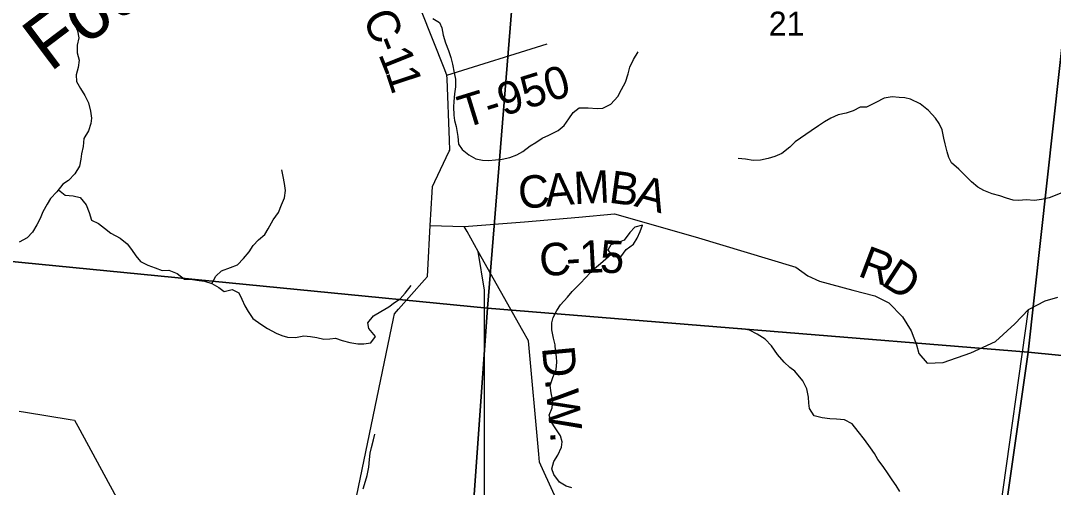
# Model space of a CAD drawing. Extents: x 0 to 42, y 0 to 22.
# Drawn here: x 2.747 to 3.649, y 17.518 to 17.925 of the extents above; entities that cross this region are included whole.
import ezdxf

# ---------------------------------------------------------------- set-up
doc = ezdxf.new("R2010")
doc.units = 0
for name, color, linetype in [('GM_X_County_Road', 7, 'Continuous'), ('GM_X_County_Road_Text', 7, 'Continuous'), ('GM_X_Minor_Lake', 7, 'Continuous'), ('GM_X_Minor_River', 7, 'Continuous'), ('GM_X_Minor_River_Text', 7, 'Continuous'), ('GM_X_Section', 7, 'Continuous'), ('GM_X_Section_Text', 7, 'Continuous'), ('GM_X_Township_Road', 7, 'Continuous'), ('GM_X_Township_Road_Text', 7, 'Continuous')]:
    doc.layers.add(name, color=color, linetype=linetype)

msp = doc.modelspace()

# ---------------------------------------------------------------- linework, layer by layer
at = {"layer": 'GM_X_County_Road'}
for points in [[(3.00848, 17.35497), (3.07286, 17.6651), (3.07373, 17.66937), (3.07729, 17.67338), (3.09993, 17.69889), (3.10256, 17.70184), (3.10288, 17.70762), (3.10505, 17.74655), (3.10667, 17.77575), (3.10692, 17.78047), (3.10907, 17.78499), (3.12163, 17.8114), (3.1221, 17.81237), (3.12177, 17.82102), (3.11976, 17.87459), (3.11963, 17.8779), (3.11725, 17.88388), (3.09745, 17.93368)], [(3.10505, 17.74655), (3.13476, 17.74555), (3.1874, 17.74956), (3.23481, 17.75389), (3.26596, 17.75674), (3.33644, 17.73665), (3.42456, 17.71011), (3.43499, 17.70257), (3.44523, 17.69788), (3.47439, 17.69006), (3.49352, 17.68503), (3.50584, 17.67883), (3.51762, 17.66675), (3.52524, 17.65447), (3.52983, 17.64217), (3.53195, 17.63459), (3.53917, 17.62609), (3.55316, 17.62692), (3.57734, 17.63519), (3.59905, 17.64515), (3.61582, 17.66059), (3.62787, 17.67316), (3.64222, 17.68062), (3.65336, 17.6839)]]:
    msp.add_lwpolyline(points, dxfattribs=at)
at = {"layer": 'GM_X_Minor_Lake'}
for points in [[(3.28846, 17.74113), (3.29037, 17.74668), (3.28393, 17.74519), (3.27956, 17.74028), (3.27462, 17.73366), (3.26856, 17.73141), (3.26288, 17.72954), (3.26021, 17.725)], [(3.26021, 17.725), (3.26473, 17.71948), (3.27154, 17.71908), (3.27629, 17.72551), (3.28255, 17.73022), (3.28598, 17.73532), (3.28846, 17.74113)]]:
    msp.add_lwpolyline(points, dxfattribs=at)
at = {"layer": 'GM_X_Minor_River'}
for points in [[(2.79376, 17.9277), (2.79431, 17.92277), (2.79674, 17.9165), (2.79785, 17.91043), (2.79651, 17.90418), (2.79667, 17.89736), (2.79816, 17.8911), (2.79738, 17.88447), (2.79565, 17.87822), (2.79601, 17.87234), (2.79939, 17.86627), (2.80334, 17.86019), (2.80635, 17.85373), (2.80821, 17.84652), (2.80913, 17.84026), (2.80855, 17.83553), (2.80644, 17.82909), (2.80226, 17.82266), (2.80167, 17.81565), (2.80032, 17.80921), (2.79973, 17.80448), (2.79858, 17.79823), (2.79439, 17.79161), (2.78888, 17.78594), (2.78395, 17.78274), (2.77882, 17.77594), (2.77331, 17.77008), (2.77027, 17.76517), (2.76665, 17.75855), (2.76417, 17.75249), (2.76131, 17.74719), (2.75751, 17.74076), (2.75295, 17.73567), (2.74575, 17.7319)], [(3.10737, 17.92744), (3.11303, 17.92401), (3.11509, 17.91926), (3.11639, 17.91281), (3.11845, 17.90617), (3.12107, 17.89934), (3.12294, 17.89326), (3.12443, 17.88738), (3.12592, 17.87998), (3.12703, 17.87429), (3.1272, 17.86766), (3.12623, 17.8616), (3.12564, 17.85478), (3.12524, 17.85004), (3.12578, 17.84303), (3.12633, 17.8381), (3.12764, 17.83297), (3.12912, 17.82425), (3.12966, 17.81761), (3.13286, 17.81286), (3.13871, 17.80829), (3.14475, 17.80467), (3.15061, 17.80351), (3.1559, 17.8033), (3.16196, 17.80384), (3.16782, 17.80439), (3.17445, 17.80588), (3.1807, 17.80832), (3.18582, 17.81114), (3.19227, 17.81605), (3.19738, 17.81906), (3.20288, 17.82283), (3.20876, 17.82546), (3.21672, 17.82941), (3.22203, 17.83394), (3.22621, 17.8398), (3.23001, 17.84509), (3.23514, 17.84943), (3.24289, 17.8494), (3.25083, 17.84861), (3.25594, 17.84916), (3.26295, 17.85255), (3.26884, 17.85916), (3.27227, 17.8654), (3.27551, 17.87164), (3.278, 17.87902), (3.27953, 17.88489), (3.28277, 17.89151), (3.28677, 17.89832)], [(3.65687, 17.77491), (3.6457, 17.77079), (3.63908, 17.76911), (3.63303, 17.76838), (3.62585, 17.76879), (3.61942, 17.76844), (3.61432, 17.76866), (3.60866, 17.77039), (3.60262, 17.77231), (3.59602, 17.77423), (3.58866, 17.77711), (3.58357, 17.77998), (3.57811, 17.78455), (3.57171, 17.79102), (3.56682, 17.7956), (3.5606, 17.80131), (3.55817, 17.80606), (3.55668, 17.81099), (3.55501, 17.81783), (3.55389, 17.82276), (3.55241, 17.82997), (3.54979, 17.83548), (3.5466, 17.84042), (3.54039, 17.84708), (3.53305, 17.8528), (3.52475, 17.85682), (3.51965, 17.85798), (3.51474, 17.85838), (3.50851, 17.85879), (3.5017, 17.85768), (3.49431, 17.85411), (3.48636, 17.84998), (3.48069, 17.84982), (3.47463, 17.84681), (3.46838, 17.84476), (3.46139, 17.84327), (3.45495, 17.84027), (3.44945, 17.83707), (3.44415, 17.83368), (3.43789, 17.82916), (3.43316, 17.82615)], [(3.43316, 17.82615), (3.42388, 17.81952)], [(3.42388, 17.81952), (3.41924, 17.8148), (3.41223, 17.80952), (3.40616, 17.80689), (3.40029, 17.80501), (3.39367, 17.80371), (3.38723, 17.80336), (3.38043, 17.80433), (3.37419, 17.80492)], [(2.91412, 17.69588), (2.91758, 17.70224), (2.9227, 17.70677), (2.93047, 17.70978), (2.93653, 17.71222), (2.94184, 17.71769), (2.94678, 17.72355), (2.95021, 17.72903), (2.95495, 17.73394), (2.96046, 17.73866), (2.96331, 17.74358), (2.96788, 17.75152), (2.97245, 17.75795), (2.97493, 17.76457), (2.9776, 17.77081), (2.97857, 17.77707), (2.97765, 17.78332), (2.97653, 17.7892), (2.97523, 17.79527)], [(2.78023, 17.77781), (2.786, 17.77288), (2.79299, 17.77247), (2.79923, 17.77093), (2.8045, 17.76447), (2.80694, 17.75782), (2.80918, 17.75118), (2.81504, 17.74813), (2.82051, 17.74431), (2.82598, 17.73993), (2.83409, 17.73535), (2.84032, 17.7304), (2.84408, 17.72546), (2.84784, 17.71995), (2.85199, 17.71519), (2.85822, 17.71195), (2.86464, 17.70946), (2.87087, 17.70716), (2.87674, 17.70752), (2.88391, 17.70446), (2.89033, 17.69951), (2.89732, 17.69929), (2.903, 17.69851), (2.90791, 17.69792), (2.91434, 17.69581), (2.92019, 17.69219), (2.92509, 17.68895), (2.93191, 17.69063), (2.93776, 17.68776), (2.94039, 17.68226), (2.94301, 17.67618), (2.94583, 17.67124), (2.94997, 17.66516), (2.95695, 17.66021), (2.9628, 17.65658), (2.97035, 17.65238), (2.97526, 17.65028), (2.98037, 17.64893), (2.98736, 17.64853), (2.99456, 17.65021), (3.00042, 17.64962), (3.0059, 17.64865), (3.01214, 17.6473), (3.01743, 17.64746), (3.02235, 17.64801), (3.02821, 17.6461), (3.03482, 17.64418), (3.04182, 17.6432), (3.04693, 17.64318), (3.05317, 17.64411), (3.05716, 17.6494), (3.05133, 17.65662), (3.0504, 17.66136), (3.05553, 17.6676), (3.06178, 17.67137), (3.0688, 17.67551), (3.07392, 17.67928), (3.07866, 17.68229), (3.08322, 17.68739), (3.08835, 17.6942)], [(3.2288, 17.51739), (3.22389, 17.51874), (3.21785, 17.52217), (3.21296, 17.52902), (3.21127, 17.53395), (3.213, 17.54039), (3.21661, 17.54587), (3.21985, 17.55268), (3.22025, 17.55742), (3.21894, 17.56273), (3.21405, 17.56976), (3.21086, 17.5747), (3.20899, 17.58077), (3.21166, 17.58721), (3.21225, 17.59327), (3.21057, 17.60029), (3.20984, 17.60673), (3.21214, 17.61374), (3.21519, 17.62055), (3.21578, 17.62699), (3.21523, 17.63173), (3.21449, 17.63723), (3.21413, 17.64216), (3.21283, 17.64804), (3.21115, 17.65525), (3.21118, 17.66132), (3.21252, 17.66624), (3.21557, 17.6721), (3.21899, 17.67721), (3.22488, 17.68382), (3.22906, 17.68892), (3.23551, 17.69534), (3.24159, 17.70157), (3.24691, 17.70742), (3.25393, 17.71327), (3.26324, 17.72131)], [(3.4236, 17.61937), (3.41929, 17.62242), (3.41439, 17.62718), (3.40855, 17.63383), (3.40309, 17.64144), (3.39763, 17.64714), (3.39083, 17.65153), (3.38404, 17.65516), (3.37742, 17.65632)], [(3.51533, 17.51399), (3.51214, 17.51931), (3.50857, 17.52425), (3.50519, 17.52957), (3.50069, 17.53604), (3.49599, 17.54213), (3.49318, 17.54726), (3.48961, 17.5522), (3.48435, 17.55943), (3.4789, 17.56646), (3.47364, 17.57331), (3.46704, 17.57675), (3.46005, 17.57735), (3.45419, 17.57757), (3.44758, 17.57836), (3.44059, 17.58028), (3.43628, 17.58656), (3.43573, 17.5913), (3.43556, 17.59661), (3.43408, 17.60382), (3.43071, 17.61066), (3.4236, 17.61937)], [(3.04646, 17.51639), (3.04856, 17.52301), (3.0499, 17.52794), (3.05126, 17.53532), (3.05185, 17.54214), (3.05262, 17.54745), (3.05359, 17.55256), (3.05532, 17.55919), (3.05666, 17.56411)]]:
    msp.add_lwpolyline(points, dxfattribs=at)
at = {"layer": 'GM_X_Section'}
for points in [[(2.65705, 18.24703), (3.1993, 18.2215), (3.15501, 17.67437), (2.6558, 17.7233)], [(3.68779, 18.18177), (3.62739, 17.63591), (3.15501, 17.67437), (3.1993, 18.2215)], [(4.15734, 18.14567), (4.09844, 17.5892), (3.62739, 17.63591), (3.68779, 18.18177)], [(3.15501, 17.67437), (3.12245, 17.21832), (2.6195, 17.19491), (2.6558, 17.7233)], [(3.62739, 17.63591), (3.55355, 17.11809), (3.34068, 17.13624), (3.12245, 17.21832), (3.15501, 17.67437)], [(4.09844, 17.5892), (4.04585, 17.11171), (3.55355, 17.11809), (3.62739, 17.63591)]]:
    msp.add_lwpolyline(points, close=True, dxfattribs=at)
at = {"layer": 'GM_X_Township_Road'}
for p, q in [((3.11963, 17.8779), (3.20707, 17.90524)), ((3.55654, 17.17046), (3.62787, 17.67316))]:
    msp.add_line(p, q, dxfattribs=at)
for points in [[(3.52952, 17.02331), (3.52666, 17.02738), (3.45817, 17.12517), (3.42107, 17.17814), (3.41856, 17.18167), (3.41525, 17.18619), (3.27683, 17.37464), (3.27403, 17.37842), (3.27186, 17.38317), (3.20163, 17.53705), (3.20043, 17.53965), (3.19979, 17.5467), (3.19079, 17.6458), (3.18599, 17.65449), (3.14697, 17.72388), (3.13722, 17.74122), (3.13476, 17.74555)], [(3.12722, 17.27082), (3.13348, 17.27102), (3.14087, 17.27126), (3.14827, 17.27151), (3.15257, 17.33628), (3.15257, 17.69001), (3.14697, 17.72388)], [(2.74578, 17.5843), (2.75132, 17.58341), (2.79035, 17.57712), (2.79414, 17.57651), (2.79702, 17.5712), (2.85357, 17.46694), (2.85541, 17.46351), (2.85956, 17.45917), (2.90741, 17.40918), (2.90776, 17.40882), (2.91479, 17.40261), (2.95558, 17.36666), (2.9586, 17.364), (2.96436, 17.36295), (3.00327, 17.35592), (3.00848, 17.35497)]]:
    msp.add_lwpolyline(points, dxfattribs=at)

# ---------------------------------------------------------------- texts
at = {"layer": 'GM_X_County_Road_Text'}
for s, rotation, p in [('C', 294.83157, (3.04537, 17.92783)), ('-', 292.029, (3.05503, 17.90699)), ('1', 291.82364, (3.05939, 17.8962)), ('1', 288.22762, (3.06574, 17.8804)), ('M', 2.84544, (3.23089, 17.765)), ('B', 352.21708, (3.2603, 17.76659)), ('C', 4.93153, (3.18301, 17.76087)), ('A', 4.93057, (3.20626, 17.76287)), ('A', 344.98035, (3.28249, 17.76362)), ('C', 4.80221, (3.20148, 17.7018)), ('1', 2.91022, (3.23611, 17.70463)), ('5', 357.13136, (3.25283, 17.70552)), ('R', 339.2626, (3.47767, 17.70277)), ('-', 4.40709, (3.22468, 17.70375)), ('D', 327.08487, (3.49807, 17.69523))]:
    msp.add_text(s, height=0.02841, rotation=rotation, dxfattribs=at).set_placement(p)
at = {"layer": 'GM_X_Minor_River_Text'}
msp.add_text('Fourmile', height=0.047349, rotation=37.00209, dxfattribs=at).set_placement((2.77284, 17.87994))
at = {"layer": 'GM_X_Section_Text'}
msp.add_text('21', height=0.020928, rotation=0.00001, dxfattribs=at).set_placement((3.40085, 17.91242))
at = {"layer": 'GM_X_Township_Road_Text'}
for s, rotation, p in [('T-950', 17.1021, (3.13472, 17.83135)), ('D.W.', 275.36511, (3.2026, 17.63994))]:
    msp.add_text(s, height=0.028409, rotation=rotation, dxfattribs=at).set_placement(p)

doc.saveas('drawing.dxf')
